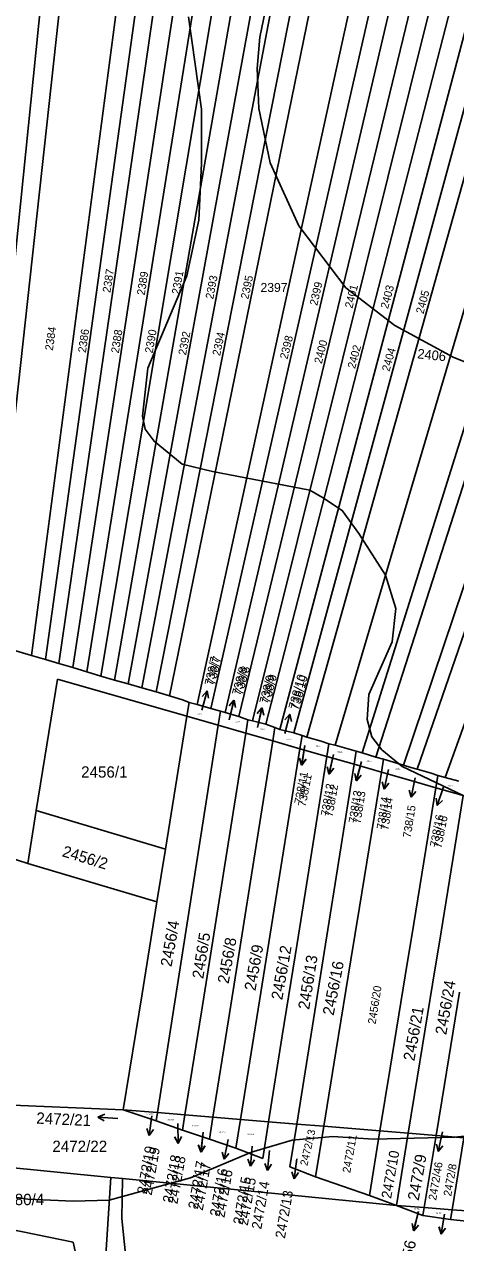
# Model space of a CAD drawing. Extents: x -555860 to -552701, y -1187050 to -1182291.
# Drawn here: x -554299.5 to -554234.9, y -1185576 to -1185393.3 of the extents above; entities that cross this region are included whole.
import ezdxf

# ---------------------------------------------------------------- set-up
doc = ezdxf.new("R2010")
doc.units = 0
for name, color, linetype in [('LEG_2b', 7, 'Continuous'), ('Level 16', 7, 'Continuous'), ('Level 40', 7, 'Continuous'), ('Level 41', 7, 'Continuous'), ('navrh_BV', 7, 'Continuous'), ('stav_BV', 7, 'Continuous')]:
    doc.layers.add(name, color=color, linetype=linetype)

msp = doc.modelspace()

# ---------------------------------------------------------------- linework, layer by layer
at = {"layer": 'Level 16'}
for p, q in [((-554272.89, -1185496.14), (-554272.11, -1185493.24)), ((-554272.11, -1185493.24), (-554272.85, -1185494.08)), ((-554272.11, -1185493.24), (-554271.88, -1185494.34)), ((-554268.09, -1185494.67), (-554268.81, -1185495.52)), ((-554268.8, -1185497.58), (-554268.09, -1185494.67)), ((-554268.09, -1185494.67), (-554267.84, -1185495.76)), ((-554263.89, -1185495.8), (-554264.6, -1185496.67)), ((-554264.55, -1185498.73), (-554263.89, -1185495.8)), ((-554263.89, -1185495.8), (-554263.62, -1185496.89)), ((-554260.47, -1185499.67), (-554259.71, -1185496.77)), ((-554259.71, -1185496.77), (-554260.45, -1185497.61)), ((-554259.71, -1185496.77), (-554259.48, -1185497.86)), ((-554257.46, -1185501.46), (-554257.95, -1185504.42)), ((-554257.95, -1185504.42), (-554258.28, -1185503.35)), ((-554257.95, -1185504.42), (-554257.29, -1185503.52)), ((-554253.16, -1185502.81), (-554253.84, -1185505.73)), ((-554253.84, -1185505.73), (-554254.1, -1185504.65)), ((-554253.84, -1185505.73), (-554253.12, -1185504.87)), ((-554248.97, -1185503.85), (-554249.73, -1185506.75)), ((-554244.93, -1185505.05), (-554245.58, -1185507.98)), ((-554249.73, -1185506.75), (-554249.96, -1185505.66)), ((-554249.73, -1185506.75), (-554249, -1185505.91)), ((-554245.58, -1185507.98), (-554245.85, -1185506.9)), ((-554245.58, -1185507.98), (-554244.87, -1185507.11)), ((-554240.9, -1185506.29), (-554241.53, -1185509.22)), ((-554241.53, -1185509.22), (-554241.81, -1185508.14)), ((-554241.53, -1185509.22), (-554240.83, -1185508.35)), ((-554236.66, -1185507.63), (-554237.64, -1185510.47)), ((-554237.64, -1185510.47), (-554237.79, -1185509.36)), ((-554237.64, -1185510.47), (-554236.84, -1185509.68)), ((-554288.48, -1185557.19), (-554287.45, -1185556.76)), ((-554285.49, -1185557.4), (-554288.48, -1185557.19)), ((-554288.48, -1185557.19), (-554287.52, -1185557.76)), ((-554280.38, -1185556.99), (-554280.78, -1185559.96)), ((-554276.51, -1185558.12), (-554276.43, -1185561.12)), ((-554280.78, -1185559.96), (-554281.14, -1185558.91)), ((-554280.78, -1185559.96), (-554280.15, -1185559.04)), ((-554276.43, -1185561.12), (-554276.96, -1185560.13)), ((-554276.43, -1185561.12), (-554275.96, -1185560.11)), ((-554272.71, -1185559.43), (-554273.04, -1185562.41)), ((-554236.8, -1185559.41), (-554237.48, -1185562.33)), ((-554273.04, -1185562.41), (-554273.43, -1185561.36)), ((-554273.04, -1185562.41), (-554272.43, -1185561.47)), ((-554268.97, -1185560.56), (-554269.53, -1185563.51)), ((-554265.35, -1185561.53), (-554265.6, -1185564.52)), ((-554262.78, -1185562.21), (-554263.05, -1185565.2)), ((-554237.48, -1185562.33), (-554237.74, -1185561.24)), ((-554237.48, -1185562.33), (-554236.77, -1185561.47)), ((-554269.53, -1185563.51), (-554269.83, -1185562.43)), ((-554269.53, -1185563.51), (-554268.85, -1185562.62)), ((-554265.6, -1185564.52), (-554266.01, -1185563.48)), ((-554265.6, -1185564.52), (-554265.02, -1185563.57)), ((-554258.67, -1185563.46), (-554259.06, -1185566.44)), ((-554263.05, -1185565.2), (-554263.46, -1185564.16)), ((-554263.05, -1185565.2), (-554262.46, -1185564.25)), ((-554259.06, -1185566.44), (-554259.43, -1185565.38)), ((-554259.06, -1185566.44), (-554258.43, -1185565.51)), ((-554240.42, -1185571.32), (-554241.12, -1185574.24)), ((-554241.12, -1185574.24), (-554241.37, -1185573.15)), ((-554236.5, -1185571.76), (-554237.03, -1185574.71)), ((-554241.12, -1185574.24), (-554240.4, -1185573.38)), ((-554237.03, -1185574.71), (-554237.35, -1185573.64)), ((-554237.03, -1185574.71), (-554236.36, -1185573.82))]:
    msp.add_line(p, q, dxfattribs=at)
at = {"layer": 'Level 40'}
for points in [[(-554264.2, -1185395.2), (-554262.26, -1185385.77), (-554260.39, -1185380.5), (-554258.52, -1185376.9), (-554255.77, -1185372.58), (-554252.28, -1185368.44), (-554245.76, -1185361.43), (-554243.41, -1185355.73), (-554222.89, -1185337.38), (-554219.7, -1185335.72), (-554214.7, -1185334.47), (-554209.71, -1185334.61), (-554205.28, -1185335.58), (-554178.65, -1185344.59), (-554152.03, -1185350.83), (-554143.16, -1185354.44), (-554136.57, -1185358.23), (-554133.29, -1185361.24), (-554130.4, -1185363.18), (-554126.44, -1185367.14), (-554123.63, -1185370.93), (-554120.66, -1185375.39), (-554119.14, -1185378.73), (-554109.19, -1185403.32)], [(-554109.05, -1185491.29), (-554120.7, -1185495.59), (-554131.37, -1185501.27), (-554138.72, -1185503.91), (-554142.6, -1185503.63), (-554146.35, -1185502.52), (-554160.91, -1185490.18), (-554174.63, -1185476.04), (-554180.59, -1185470.91), (-554189.19, -1185464.81), (-554208.05, -1185454.13), (-554235.23, -1185443.18), (-554243.96, -1185438.46), (-554251.31, -1185432.78), (-554258.38, -1185423.49), (-554262.68, -1185414.06), (-554264.35, -1185405.91), (-554264.62, -1185399.92), (-554264.2, -1185395.2)]]:
    msp.add_lwpolyline(points, dxfattribs=at)
at = {"layer": 'Level 41'}
for points in [[(-554280.98, -1185444.84), (-554275.16, -1185430.98), (-554273.36, -1185422.66), (-554272.93, -1185414.16), (-554272.94, -1185406.02), (-554274.88, -1185392.15)], [(-554216.37, -1185517.22), (-554242.85, -1185504.6), (-554245.9, -1185502.09), (-554247.43, -1185500.17), (-554248.12, -1185497.53), (-554247.84, -1185493.79), (-554244.38, -1185485.88), (-554243.82, -1185480.89), (-554245.35, -1185475.9), (-554249.36, -1185469.67), (-554251.86, -1185466.19), (-554254.81, -1185464.23), (-554256.72, -1185463.15), (-554271.28, -1185460.37), (-554275.85, -1185459.27), (-554280.06, -1185455.81), (-554281.4, -1185453.99), (-554281.81, -1185452.05), (-554280.98, -1185444.84)], [(-554328.82, -1185580.45), (-554321.64, -1185568.86), (-554316.61, -1185566.81), (-554299.01, -1185569.5), (-554292.17, -1185569.8), (-554286.81, -1185569.63), (-554274.6, -1185566.3), (-554265.45, -1185562.42), (-554259.35, -1185560.62), (-554253.25, -1185560.07), (-554247.15, -1185560.48), (-554234.95, -1185560.2), (-554219.7, -1185558.54), (-554207.49, -1185556.04), (-554198.34, -1185553.27), (-554189.19, -1185549.39), (-554183.37, -1185548.28), (-554180.32, -1185548.56), (-554176.85, -1185550.08), (-554172.28, -1185554.38), (-554169.78, -1185557.71), (-554163.64, -1185564.77), (-554158.22, -1185571.5), (-554154.1, -1185578.8)]]:
    msp.add_lwpolyline(points, dxfattribs=at)
at = {"layer": 'navrh_BV'}
for p, q in [((-554306.73, -1185485.49), (-554295.41, -1185374.12)), ((-554292.44, -1185374.33), (-554304.67, -1185486.1)), ((-554298.46, -1185487.94), (-554283.58, -1185375.05)), ((-554280.7, -1185375.84), (-554296.36, -1185488.55)), ((-554294.35, -1185489.16), (-554278.01, -1185376.52)), ((-554275.02, -1185377.28), (-554292.24, -1185489.74)), ((-554290.13, -1185490.42), (-554272.14, -1185378.12)), ((-554269.26, -1185378.83), (-554288.04, -1185491.05)), ((-554286.01, -1185491.67), (-554266.43, -1185379.67)), ((-554263.53, -1185380.45), (-554283.97, -1185492.19)), ((-554281.88, -1185492.81), (-554260.65, -1185381.21)), ((-554257.75, -1185381.96), (-554279.76, -1185493.42)), ((-554277.76, -1185494.01), (-554254.98, -1185382.73)), ((-554273.58, -1185495.28), (-554249.28, -1185384.3)), ((-554246.38, -1185385.16), (-554271.54, -1185495.89)), ((-554269.39, -1185496.52), (-554243.55, -1185385.89)), ((-554240.62, -1185386.64), (-554267.35, -1185497.11)), ((-554265.3, -1185497.74), (-554237.83, -1185387.46)), ((-554234.95, -1185388.29), (-554263.3, -1185498.26)), ((-554261.23, -1185499.06), (-554232.05, -1185389.12)), ((-554229.22, -1185389.88), (-554259.09, -1185499.53)), ((-554257.14, -1185500.2), (-554226.4, -1185390.71)), ((-554252.91, -1185501.41), (-554220.62, -1185392.2)), ((-554248.85, -1185502.56), (-554214.79, -1185393.8)), ((-554211.96, -1185394.51), (-554246.79, -1185503.18)), ((-554242.67, -1185504.38), (-554206.24, -1185396.12)), ((-554203.39, -1185396.92), (-554240.61, -1185504.98)), ((-554197.65, -1185398.48), (-554236.44, -1185506.24)), ((-554298.46, -1185487.94), (-554302.63, -1185486.72)), ((-554296.36, -1185488.55), (-554298.46, -1185487.94)), ((-554294.35, -1185489.16), (-554296.36, -1185488.55)), ((-554292.24, -1185489.74), (-554294.35, -1185489.16)), ((-554290.13, -1185490.42), (-554292.24, -1185489.74)), ((-554288.04, -1185491.05), (-554290.13, -1185490.42)), ((-554297.73, -1185511.18), (-554294.56, -1185491.49)), ((-554294.56, -1185491.49), (-554275.14, -1185497.07)), ((-554286.01, -1185491.67), (-554288.04, -1185491.05)), ((-554283.97, -1185492.19), (-554286.01, -1185491.67)), ((-554281.88, -1185492.81), (-554283.97, -1185492.19)), ((-554279.76, -1185493.42), (-554281.88, -1185492.81)), ((-554277.76, -1185494.01), (-554279.76, -1185493.42)), ((-554275.67, -1185494.65), (-554277.76, -1185494.01)), ((-554274.8, -1185494.98), (-554275.67, -1185494.65)), ((-554275.14, -1185497.07), (-554274.8, -1185494.98)), ((-554273.58, -1185495.28), (-554274.8, -1185494.98)), ((-554271.54, -1185495.89), (-554273.58, -1185495.28)), ((-554270.09, -1185496.28), (-554271.54, -1185495.89)), ((-554270.09, -1185496.28), (-554270.43, -1185498.42)), ((-554269.39, -1185496.52), (-554270.09, -1185496.28)), ((-554278.36, -1185516.99), (-554275.14, -1185497.07)), ((-554275.14, -1185497.07), (-554270.43, -1185498.42)), ((-554267.35, -1185497.11), (-554269.39, -1185496.52)), ((-554265.98, -1185497.58), (-554267.35, -1185497.11)), ((-554266.3, -1185499.6), (-554265.98, -1185497.58)), ((-554265.3, -1185497.74), (-554265.98, -1185497.58)), ((-554263.3, -1185498.26), (-554265.3, -1185497.74)), ((-554261.95, -1185498.74), (-554263.3, -1185498.26)), ((-554279.56, -1185556.52), (-554270.43, -1185498.42)), ((-554270.43, -1185498.42), (-554266.3, -1185499.6)), ((-554269.5, -1185519.65), (-554266.3, -1185499.6)), ((-554266.3, -1185499.6), (-554262.27, -1185500.76)), ((-554261.95, -1185498.74), (-554262.27, -1185500.76)), ((-554261.23, -1185499.06), (-554261.95, -1185498.74)), ((-554259.09, -1185499.53), (-554261.23, -1185499.06)), ((-554257.87, -1185499.94), (-554259.09, -1185499.53)), ((-554258.19, -1185501.93), (-554257.87, -1185499.94)), ((-554257.14, -1185500.2), (-554257.87, -1185499.94)), ((-554267.11, -1185557.53), (-554258.19, -1185501.93)), ((-554262.27, -1185500.76), (-554265.47, -1185520.86)), ((-554262.27, -1185500.76), (-554258.19, -1185501.93)), ((-554258.19, -1185501.93), (-554254.14, -1185503.09)), ((-554255, -1185500.82), (-554257.14, -1185500.2)), ((-554253.84, -1185501.19), (-554255, -1185500.82)), ((-554253.84, -1185501.19), (-554254.14, -1185503.09)), ((-554252.91, -1185501.41), (-554253.84, -1185501.19)), ((-554249.75, -1185502.3), (-554252.91, -1185501.41)), ((-554254.14, -1185503.09), (-554257.37, -1185523.28)), ((-554254.14, -1185503.09), (-554250.06, -1185504.27)), ((-554250.06, -1185504.27), (-554249.75, -1185502.3)), ((-554248.85, -1185502.56), (-554249.75, -1185502.3)), ((-554246.79, -1185503.18), (-554248.85, -1185502.56)), ((-554245.65, -1185503.5), (-554246.79, -1185503.18)), ((-554245.65, -1185503.5), (-554245.97, -1185505.44)), ((-554242.67, -1185504.38), (-554245.65, -1185503.5)), ((-554258.68, -1185558.22), (-554250.06, -1185504.27)), ((-554250.06, -1185504.27), (-554245.97, -1185505.44)), ((-554245.97, -1185505.44), (-554249.26, -1185525.72)), ((-554245.97, -1185505.44), (-554241.9, -1185506.61)), ((-554241.59, -1185504.73), (-554242.67, -1185504.38)), ((-554240.61, -1185504.98), (-554241.59, -1185504.73)), ((-554238.52, -1185505.61), (-554240.61, -1185504.98)), ((-554237.52, -1185505.94), (-554238.52, -1185505.61)), ((-554241.9, -1185506.61), (-554237.82, -1185507.78)), ((-554237.52, -1185505.94), (-554237.82, -1185507.78)), ((-554236.44, -1185506.24), (-554237.52, -1185505.94)), ((-554234.36, -1185506.81), (-554236.44, -1185506.24)), ((-554330.26, -1185509), (-554299.01, -1185519.14)), ((-554237.82, -1185507.78), (-554241.13, -1185528.15)), ((-554237.82, -1185507.78), (-554233.72, -1185508.96)), ((-554237.04, -1185529.38), (-554233.72, -1185508.96)), ((-554299.01, -1185519.14), (-554297.73, -1185511.18)), ((-554297.73, -1185511.18), (-554278.36, -1185516.99)), ((-554279.64, -1185524.91), (-554278.36, -1185516.99)), ((-554299.01, -1185519.14), (-554279.64, -1185524.91)), ((-554270.77, -1185527.56), (-554269.5, -1185519.65)), ((-554265.47, -1185520.86), (-554266.72, -1185528.76)), ((-554257.37, -1185523.28), (-554258.63, -1185531.17)), ((-554281.87, -1185538.72), (-554279.64, -1185524.91)), ((-554249.26, -1185525.72), (-554250.54, -1185533.58)), ((-554272.97, -1185541.38), (-554270.77, -1185527.56)), ((-554266.72, -1185528.76), (-554268.92, -1185542.59)), ((-554241.13, -1185528.15), (-554242.41, -1185536.01)), ((-554258.63, -1185531.17), (-554260.84, -1185545.01)), ((-554238.32, -1185537.23), (-554237.04, -1185529.38)), ((-554250.54, -1185533.58), (-554252.79, -1185547.41)), ((-554242.41, -1185536.01), (-554244.66, -1185549.84)), ((-554240.57, -1185551.07), (-554238.32, -1185537.23)), ((-554234.25, -1185538.44), (-554236.52, -1185552.28)), ((-554284.68, -1185556.1), (-554281.87, -1185538.72)), ((-554275.44, -1185556.85), (-554272.97, -1185541.38)), ((-554268.92, -1185542.59), (-554271.24, -1185557.2)), ((-554260.84, -1185545.01), (-554262.9, -1185557.88)), ((-554252.79, -1185547.41), (-554254.61, -1185558.55)), ((-554244.66, -1185549.84), (-554246.19, -1185559.24)), ((-554241.96, -1185559.58), (-554240.57, -1185551.07)), ((-554236.52, -1185552.28), (-554237.78, -1185559.93)), ((-554284.68, -1185556.1), (-554323.36, -1185554.5)), ((-554284.68, -1185556.1), (-554279.76, -1185557.76)), ((-554279.56, -1185556.52), (-554284.68, -1185556.1)), ((-554279.56, -1185556.52), (-554279.76, -1185557.76)), ((-554275.44, -1185556.85), (-554279.56, -1185556.52)), ((-554279.76, -1185557.76), (-554275.81, -1185559.16)), ((-554275.81, -1185559.16), (-554275.44, -1185556.85)), ((-554271.24, -1185557.2), (-554275.44, -1185556.85)), ((-554271.24, -1185557.2), (-554271.77, -1185560.5)), ((-554267.11, -1185557.53), (-554271.24, -1185557.2)), ((-554267.8, -1185561.85), (-554267.11, -1185557.53)), ((-554262.9, -1185557.88), (-554267.11, -1185557.53)), ((-554262.9, -1185557.88), (-554263.78, -1185563.37)), ((-554258.68, -1185558.22), (-554262.9, -1185557.88)), ((-554259.71, -1185564.66), (-554258.68, -1185558.22)), ((-554254.61, -1185558.55), (-554258.68, -1185558.22)), ((-554254.61, -1185558.55), (-554255.84, -1185566.14)), ((-554254.61, -1185558.55), (-554246.19, -1185559.24)), ((-554275.81, -1185559.16), (-554271.77, -1185560.5)), ((-554246.19, -1185559.24), (-554247.77, -1185568.94)), ((-554241.96, -1185559.58), (-554246.19, -1185559.24)), ((-554243.73, -1185570.45), (-554241.96, -1185559.58)), ((-554237.78, -1185559.93), (-554241.96, -1185559.58)), ((-554237.78, -1185559.93), (-554239.56, -1185570.76)), ((-554233.61, -1185560.27), (-554237.78, -1185559.93)), ((-554235.39, -1185571.07), (-554233.61, -1185560.27)), ((-554271.77, -1185560.5), (-554267.8, -1185561.85)), ((-554267.8, -1185561.85), (-554263.78, -1185563.37)), ((-554286.52, -1185566.23), (-554321.47, -1185562.78)), ((-554259.71, -1185564.66), (-554255.84, -1185566.14)), ((-554286.52, -1185566.23), (-554287.62, -1185583.18)), ((-554284.82, -1185566.4), (-554286.52, -1185566.23)), ((-554284.82, -1185566.4), (-554284.9, -1185572.37)), ((-554243.73, -1185570.45), (-554284.82, -1185566.4)), ((-554255.84, -1185566.14), (-554251.8, -1185567.54)), ((-554251.8, -1185567.54), (-554247.77, -1185568.94)), ((-554247.77, -1185568.94), (-554243.73, -1185570.45)), ((-554292.21, -1185575.92), (-554320.03, -1185570.25)), ((-554243.73, -1185570.45), (-554239.75, -1185571.92)), ((-554239.56, -1185570.76), (-554243.73, -1185570.45)), ((-554239.56, -1185570.76), (-554239.75, -1185571.92)), ((-554235.39, -1185571.07), (-554239.56, -1185570.76)), ((-554235.63, -1185572.54), (-554235.39, -1185571.07)), ((-554231.08, -1185571.39), (-554235.39, -1185571.07)), ((-554284.9, -1185572.37), (-554283.87, -1185582.54)), ((-554239.75, -1185571.92), (-554235.63, -1185572.54)), ((-554235.63, -1185572.54), (-554231.34, -1185572.98)), ((-554284.34, -1185610.24), (-554292.21, -1185575.92))]:
    msp.add_line(p, q, dxfattribs=at)
at = {"layer": 'stav_BV'}
for p, q in [((-554272.89, -1185496.14), (-554272.11, -1185493.24)), ((-554272.11, -1185493.24), (-554272.86, -1185494.08)), ((-554272.11, -1185493.24), (-554271.89, -1185494.34)), ((-554268.8, -1185497.58), (-554268.07, -1185494.67)), ((-554268.07, -1185494.67), (-554268.8, -1185495.52)), ((-554268.07, -1185494.67), (-554267.83, -1185495.76)), ((-554263.88, -1185495.81), (-554264.59, -1185496.67)), ((-554264.55, -1185498.73), (-554263.88, -1185495.81)), ((-554263.88, -1185495.81), (-554263.61, -1185496.89)), ((-554260.47, -1185499.67), (-554259.69, -1185496.77)), ((-554259.69, -1185496.77), (-554260.44, -1185497.61)), ((-554259.69, -1185496.77), (-554259.47, -1185497.87)), ((-554257.46, -1185501.46), (-554257.93, -1185504.42)), ((-554257.93, -1185504.42), (-554258.27, -1185503.36)), ((-554257.93, -1185504.42), (-554257.28, -1185503.51)), ((-554253.16, -1185502.81), (-554253.83, -1185505.73)), ((-554253.83, -1185505.73), (-554254.1, -1185504.65)), ((-554253.83, -1185505.73), (-554253.12, -1185504.87)), ((-554248.97, -1185503.85), (-554249.75, -1185506.75)), ((-554244.93, -1185505.05), (-554245.55, -1185507.99)), ((-554249.75, -1185506.75), (-554249.97, -1185505.65)), ((-554249.75, -1185506.75), (-554249, -1185505.91)), ((-554245.55, -1185507.99), (-554245.84, -1185506.9)), ((-554245.55, -1185507.99), (-554244.86, -1185507.11)), ((-554236.66, -1185507.63), (-554237.64, -1185510.47)), ((-554237.64, -1185510.47), (-554237.78, -1185509.36)), ((-554237.64, -1185510.47), (-554236.84, -1185509.68)), ((-554280.38, -1185556.99), (-554280.8, -1185559.96)), ((-554276.51, -1185558.12), (-554276.46, -1185561.12)), ((-554280.8, -1185559.96), (-554281.15, -1185558.9)), ((-554280.8, -1185559.96), (-554280.16, -1185559.04)), ((-554276.46, -1185561.12), (-554276.98, -1185560.13)), ((-554276.46, -1185561.12), (-554275.97, -1185560.11)), ((-554272.71, -1185559.43), (-554273.02, -1185562.42)), ((-554273.02, -1185562.42), (-554273.42, -1185561.37)), ((-554273.02, -1185562.42), (-554272.42, -1185561.47)), ((-554268.97, -1185560.56), (-554269.54, -1185563.51)), ((-554265.35, -1185561.53), (-554265.61, -1185564.52)), ((-554269.54, -1185563.51), (-554269.84, -1185562.43)), ((-554269.54, -1185563.51), (-554268.86, -1185562.62)), ((-554265.61, -1185564.52), (-554266.02, -1185563.48)), ((-554265.61, -1185564.52), (-554265.03, -1185563.57)), ((-554240.42, -1185571.32), (-554241.15, -1185574.23)), ((-554241.15, -1185574.23), (-554241.39, -1185573.14)), ((-554236.5, -1185571.76), (-554237.02, -1185574.72)), ((-554241.15, -1185574.23), (-554240.42, -1185573.38)), ((-554237.02, -1185574.72), (-554237.34, -1185573.64)), ((-554237.02, -1185574.72), (-554236.35, -1185573.82))]:
    msp.add_line(p, q, dxfattribs=at)

# ---------------------------------------------------------------- texts
at = {"layer": 'LEG_2b'}
for s, height, rotation, p in [('2387', 1.2, 81, (-554286.62, -1185433.6)), ('2389', 1.2, 81, (-554281.47, -1185433.97)), ('2391', 1.2, 80, (-554276.25, -1185433.86)), ('2393', 1.2, 79, (-554271.2, -1185434.57)), ('2395', 1.2, 78, (-554265.93, -1185434.57)), ('2399', 1.2, 77, (-554255.6, -1185435.54)), ('2401', 1.2, 76, (-554250.33, -1185435.95)), ('2403', 1.2, 75, (-554244.99, -1185436.03)), ('2405', 1.2, 75, (-554239.68, -1185436.8)), ('2384', 1.2, 82, (-554295.24, -1185442.27)), ('2386', 1.2, 82, (-554290.29, -1185442.6)), ('2388', 1.2, 81, (-554285.35, -1185442.68)), ('2390', 1.2, 80, (-554280.28, -1185442.68)), ('2392', 1.2, 79, (-554275.28, -1185442.97)), ('2394', 1.2, 78, (-554270.17, -1185443.08)), ('2398', 1.2, 76, (-554260.07, -1185443.59)), ('2400', 1.2, 76, (-554254.92, -1185444.26)), ('2402', 1.2, 75, (-554249.93, -1185445)), ('2404', 1.2, 74, (-554244.79, -1185445.44)), ('2406', 1.445, 354, (-554240.65, -1185443.37)), ('738/7', 1.3, 77, (-554270.91, -1185492.46)), ('738/8', 1.3, 75, (-554266.79, -1185493.94)), ('738/9', 1.3, 76, (-554262.67, -1185495.19)), ('738/10', 1.3, 75, (-554258.37, -1185496.24)), ('738/11', 1.2, 79, (-554257.34, -1185510.7)), ('738/12', 1.2, 80, (-554253.3, -1185512.22)), ('738/13', 1.2, 81, (-554249.11, -1185513.24)), ('738/14', 1.2, 82, (-554244.92, -1185514.22)), ('738/16', 1.2, 79, (-554236.97, -1185516.92)), ('2456/2', 1.7, 343, (-554293.96, -1185518.04)), ('2456/4', 1.7, 80, (-554277.45, -1185534.72)), ('2456/5', 1.7, 81, (-554272.69, -1185536.52)), ('2456/8', 1.7, 80, (-554268.89, -1185537.26)), ('2456/9', 1.7, 80, (-554264.87, -1185538.32)), ('2456/12', 1.7, 80, (-554260.85, -1185539.7)), ('2456/13', 1.7, 81, (-554256.81, -1185541.14)), ('2456/16', 1.7, 79, (-554253.15, -1185542.03)), ('2456/20', 1.2, 81, (-554246.85, -1185543.31)), ('2456/24', 1.7, 80, (-554236.26, -1185544.93)), ('2456/21', 1.7, 80, (-554241.04, -1185548.85)), ('2472/13', 1.139, 77, (-554257.08, -1185564.56)), ('2472/11', 1.2, 80, (-554250.66, -1185565.63)), ('2472/19', 1.5, 80, (-554280.43, -1185569)), ('2472/10', 1.5, 80, (-554244.53, -1185569.49)), ('2472/18', 1.5, 80, (-554276.57, -1185570.31)), ('2472/17', 1.5, 80, (-554272.77, -1185571.27)), ('2472/9', 1.7, 80, (-554240.39, -1185569.78)), ('2472/16', 1.5, 80, (-554269.52, -1185572.35)), ('2472/8', 1.2, 80, (-554235.52, -1185569.13)), ('2472/15', 1.5, 80, (-554266.02, -1185573.54))]:
    msp.add_text(s, height=height, rotation=rotation, dxfattribs=at).set_placement(p)
for s, height, p in [('2397', 1.36, (-554264.1, -1185433.43)), ('738/7', 0.2, (-554273.61, -1185496.81)), ('738/8', 0.2, (-554267.96, -1185497.97)), ('738/9', 0.2, (-554264.2, -1185499.14)), ('738/10', 0.2, (-554260.31, -1185500.62)), ('738/11', 0.2, (-554255.95, -1185501.61)), ('738/12', 0.2, (-554252.64, -1185502.51)), ('738/13', 0.2, (-554248.25, -1185503.9)), ('2456/1', 1.7, (-554291, -1185506.27)), ('738/14', 0.2, (-554243.98, -1185505.06)), ('738/16', 0.2, (-554236.07, -1185507.63)), ('2472/19', 0.2, (-554281.18, -1185556.82)), ('2472/18', 0.2, (-554278.06, -1185557.65)), ('2472/17', 0.2, (-554274.38, -1185558.57)), ('2472/16', 0.2, (-554270.31, -1185559.5)), ('2472/15', 0.2, (-554266.09, -1185559.85)), ('2472/22', 1.7, (-554295.31, -1185562.42)), ('3180/4', 1.7, (-554303.48, -1185570.39)), ('741/56', 0.2, (-554241.13, -1185571.08)), ('741/57', 0.2, (-554237.84, -1185571.74))]:
    msp.add_text(s, height=height, dxfattribs=at).set_placement(p)
at = {"layer": 'Level 16'}
for s, height, rotation, p in [('738/7', 1.3, 77.4, (-554271.25, -1185492.55)), ('738/8', 1.3, 74.7, (-554267.17, -1185494.05)), ('738/9', 1.3, 75.6, (-554263.05, -1185495.3)), ('738/10', 1.3, 74.7, (-554258.69, -1185496.12)), ('738/11', 1.2, 79.2, (-554257.88, -1185510.31)), ('738/12', 1.2, 80.1, (-554253.9, -1185512.11)), ('738/13', 1.2, 81, (-554249.72, -1185513.15)), ('738/14', 1.2, 81.9, (-554245.52, -1185514.08)), ('738/15', 1.2, 81, (-554241.59, -1185515.36)), ('738/16', 1.2, 79.2, (-554237.55, -1185516.75)), ('2472/21', 1.7, 357.3, (-554297.75, -1185558.16)), ('2472/19', 1.5, 80.1, (-554281.16, -1185568.81)), ('2472/18', 1.5, 80.1, (-554277.31, -1185570.14)), ('2472/17', 1.5, 80.1, (-554273.5, -1185571.05)), ('2472/46', 1.2, 80.1, (-554237.77, -1185569.74)), ('2472/16', 1.5, 80.1, (-554270.25, -1185572.16)), ('2472/15', 1.5, 80.1, (-554266.76, -1185573.39)), ('2472/14', 1.5, 80.1, (-554263.99, -1185574.09)), ('2472/13', 1.5, 80.1, (-554260.45, -1185575.47)), ('741/56', 1.7, 77.4, (-554242.26, -1185582.66))]:
    msp.add_text(s, height=height, rotation=rotation, dxfattribs=at).set_placement(p)

doc.saveas('drawing.dxf')
